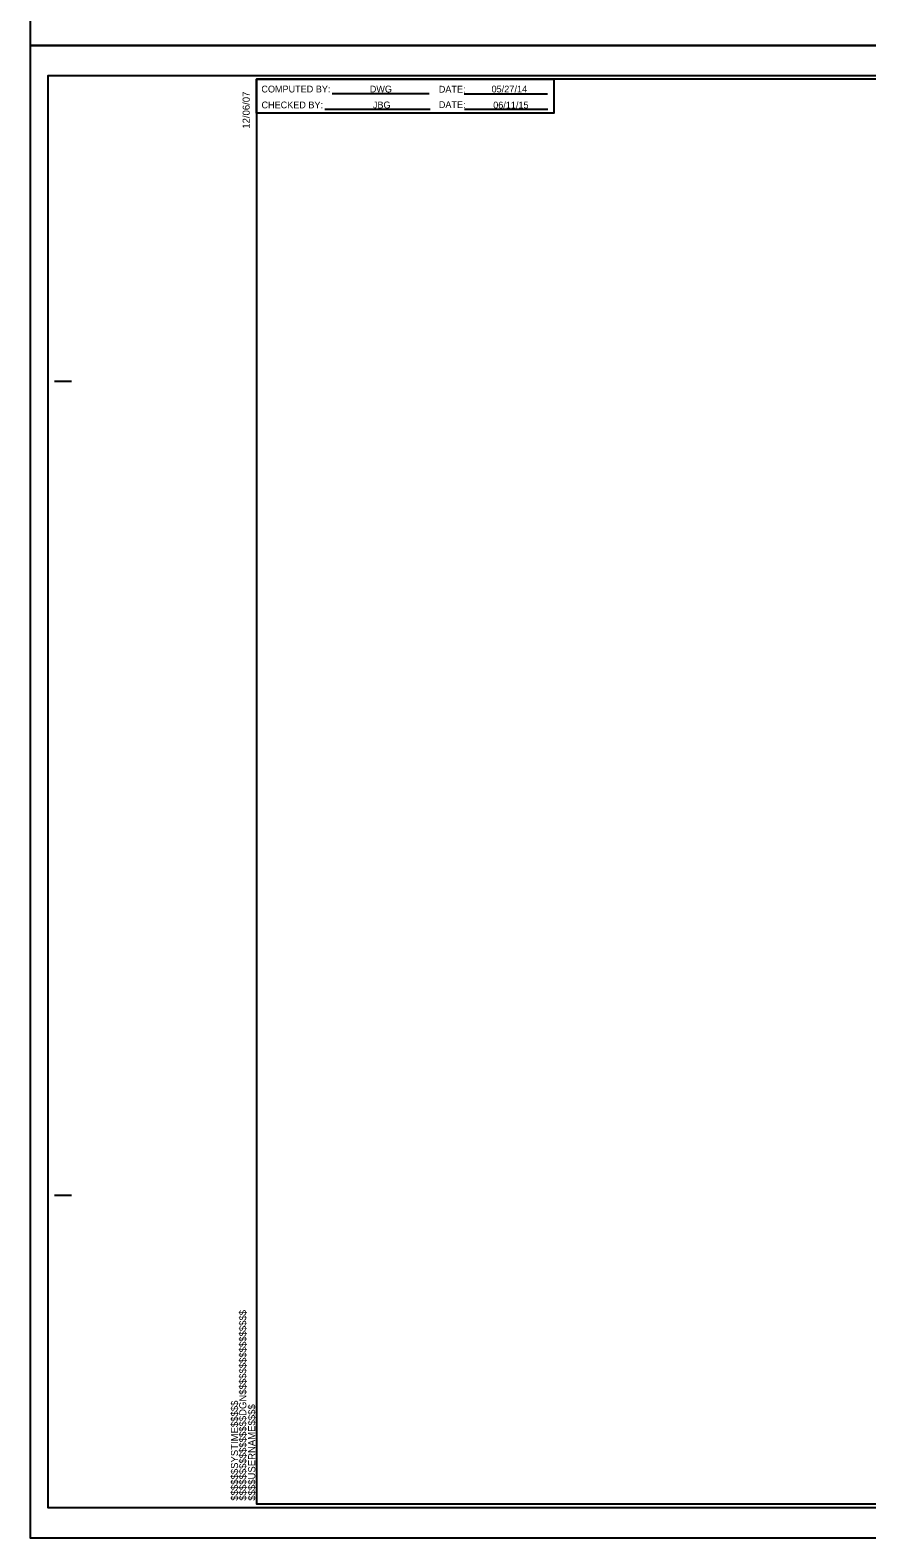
# Model space of a CAD drawing. Extents: x 1974126 to 1975810, y 438878 to 442173.
# Drawn here: x 1974126 to 1974742, y 438878 to 439990 of the extents above; entities that cross this region are included whole.
import ezdxf

# ---------------------------------------------------------------- set-up
doc = ezdxf.new("R2010")
doc.units = 0
for name, color, linetype in [('Sheet Cutting Line CELL', 7, 'Continuous'), ('Sheet Plot Border Inside CELL', 7, 'Continuous'), ('Sheet Plot Border Outside CELL', 7, 'Continuous'), ('Sheet Summary Combination CELL', 7, 'Continuous')]:
    doc.layers.add(name, color=color, linetype=linetype)

msp = doc.modelspace()

# ---------------------------------------------------------------- linework, layer by layer
at = {"layer": 'Sheet Cutting Line CELL'}
for p, q in [((1974125.6, 441078.3), (1974125.6, 439978.3)), ((1974125.6, 439978.3), (1975809.6, 439978.3)), ((1974125.6, 439978.3), (1975809.1, 439978.3)), ((1975809.6, 439978.3), (1974125.6, 439978.3)), ((1974125.6, 439978.3), (1974125.6, 438878.3)), ((1974125.6, 438878.3), (1975809.6, 438878.3))]:
    msp.add_line(p, q, dxfattribs=at)
at = {"layer": 'Sheet Plot Border Inside CELL'}
msp.add_lwpolyline([(1975805.1, 439955.8), (1974138.6, 439955.8), (1974138.6, 438900.7), (1975805.1, 438900.7)], close=True, dxfattribs=at)
at = {"layer": 'Sheet Plot Border Outside CELL'}
for points in [[(1975809.6, 441078.3), (1974125.6, 441078.3), (1974125.6, 439978.3), (1975809.6, 439978.3)], [(1975809.6, 439978.3), (1974125.6, 439978.3), (1974125.6, 438878.3), (1975809.6, 438878.3)]]:
    msp.add_lwpolyline(points, close=True, dxfattribs=at)
at = {"layer": 'Sheet Summary Combination CELL'}
for p, q in [((1974348.3, 439942.9), (1974419.8, 439942.9)), ((1974445.6, 439942.7), (1974507, 439942.7)), ((1974342.8, 439931.2), (1974420.5, 439931.2)), ((1974445.8, 439931.2), (1974507.2, 439931.2)), ((1974292.6, 439744.6), (1974292.6, 439744.6)), ((1974143.7, 439730.8), (1974156.2, 439730.8)), ((1974143.7, 439130.8), (1974156.2, 439130.8))]:
    msp.add_line(p, q, dxfattribs=at)
for points in [[(1975792.6, 439953.3), (1974292.6, 439953.3), (1974292.6, 438903.3), (1975792.6, 438903.3)], [(1974292.6, 439953.3), (1974511.6, 439953.3), (1974511.6, 439928.3), (1974292.6, 439928.3)]]:
    msp.add_lwpolyline(points, close=True, dxfattribs=at)

# ---------------------------------------------------------------- texts
for s, p in [('COMPUTED BY:', (1974296.1, 439943.6)), ('DWG', (1974376, 439943.6)), ('DATE:', (1974426.9, 439943.5)), ('05/27', (1974465.8, 439943.6)), ('/14', (1974482.7, 439943.6)), ('CHECKED BY:', (1974296.2, 439931.9)), ('JBG', (1974378.3, 439931.9)), ('DATE:', (1974426.9, 439932.1)), ('06/11/15', (1974467, 439931.8))]:
    msp.add_text(s, height=5, dxfattribs=at).set_placement(p)
for s, p in [('12/06/07', (1974287.5, 439916.9)), ('$$$$$$$$$$$$$$$$DGN$$$$$$$$$$$$$$$$', (1974285, 438905.7)), ('$$$$$$SYSTIME$$$$$', (1974278.9, 438905.7)), ('$$$$USERNAME$$$$', (1974291.6, 438905.7))]:
    msp.add_text(s, height=5.25, rotation=90, dxfattribs=at).set_placement(p)

doc.saveas('drawing.dxf')
